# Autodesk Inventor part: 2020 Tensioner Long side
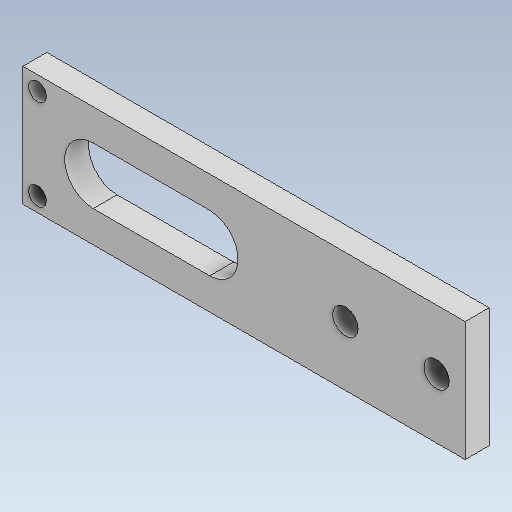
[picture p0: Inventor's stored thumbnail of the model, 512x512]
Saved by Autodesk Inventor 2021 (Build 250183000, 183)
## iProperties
Created: 2023-10
Part Number: 2020 Tensioner Long side
Material: Generico
Document SubType Name: Modeling
Designer: hp
Density: 1 g/cm^3
Appearance: Default
Author: hp
Revision Number: ANY
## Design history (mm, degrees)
feature "Solido1"
body "Solid1"
